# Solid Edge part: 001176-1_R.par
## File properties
Last saved by: morva
Revision: 82
Accuracy: 0.990
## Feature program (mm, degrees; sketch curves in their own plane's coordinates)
body "unnamed Body 1"
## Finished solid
Body 1: solid body, 165 faces, 445 edges, 284 vertices.
  Faces by surface: cylinder 70, plane 50, torus 21, cone 10, spline 10, spun 4
  Edges by curve: line 181, circle 148, spline 63, curve on surface 53
Bounding box of the edges (mm; curved faces can reach further): 94.081 x 58.368 x 55.853, from (353.4893, 364.2456, 132.335) to (447.5706, 422.614, 188.1882).
Cylindrical faces by radius (mm): R0.2 x12, R1 x2, R2 x15, R2.5 x4, R3 x9, R3.5 x5, R5 x2, R5.5 x2, R6 x8, R8 x2, R10 x4, R11 x3, R12 x1, R17 x1
Conical faces (half-angle, radius in mm at the cone's reference point): 1.3972 deg R6.4993 x3, 1.3972 deg R8.95 x2, 26.5651 deg R11.5 x3, 45 deg R4.5 x2
Toroidal faces (ring radius, tube radius in mm): R2.8 r0.2 x3, R3.2 r0.2 x3, R5 r2 x2, R6 r2 x2, R6.9506 r2 x4, R8 r2 x2, R14 r2 x2, R15 r2 x3
Planar faces by outward normal: oblique 50
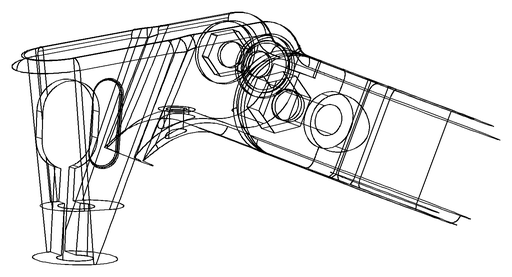
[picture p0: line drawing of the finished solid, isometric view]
